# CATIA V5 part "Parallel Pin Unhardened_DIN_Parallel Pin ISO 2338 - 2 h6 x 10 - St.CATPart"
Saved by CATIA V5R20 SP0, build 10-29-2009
Part number: Parallel Pin Unhardened_DIN_Parallel Pin ISO 2338 - 2 h6 x 10 - St
Revision: ANY
Definition: UNKNOWN
Nomenclature: Parallel Pin Unhardened_DIN_Parallel Pin ISO 2338 - 2 h6 x 10 - St
Source: Unknown
Bounding box of the stored display mesh (mm): x 0 to 10, y -1 to 1, z -1 to 1
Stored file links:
  C:\Users\Utente\Desktop\IO LAVORO\3D X SITO CF\CUMSA\3D files BA\BA 061418\Parallel Pin Unhardened_DIN_Parallel Pin ISO 2338 - 2 h6 x 10 - St.CATPart
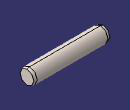
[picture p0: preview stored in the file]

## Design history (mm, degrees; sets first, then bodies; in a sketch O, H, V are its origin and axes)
Body1 "Base-Revolve" (main body)
  Solid1: solid without history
